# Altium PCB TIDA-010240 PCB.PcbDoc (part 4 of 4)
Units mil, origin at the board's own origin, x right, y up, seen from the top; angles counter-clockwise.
Board outline 5108.27 x 5374.02 mil, 4 copper layers (Top Layer, GND, PWR, Bottom Layer), stack 73.068 mil thick; 370 components, 162 nets, 1073 pads, 556 vias.
Unrouted connection lines stored in the file: 6.
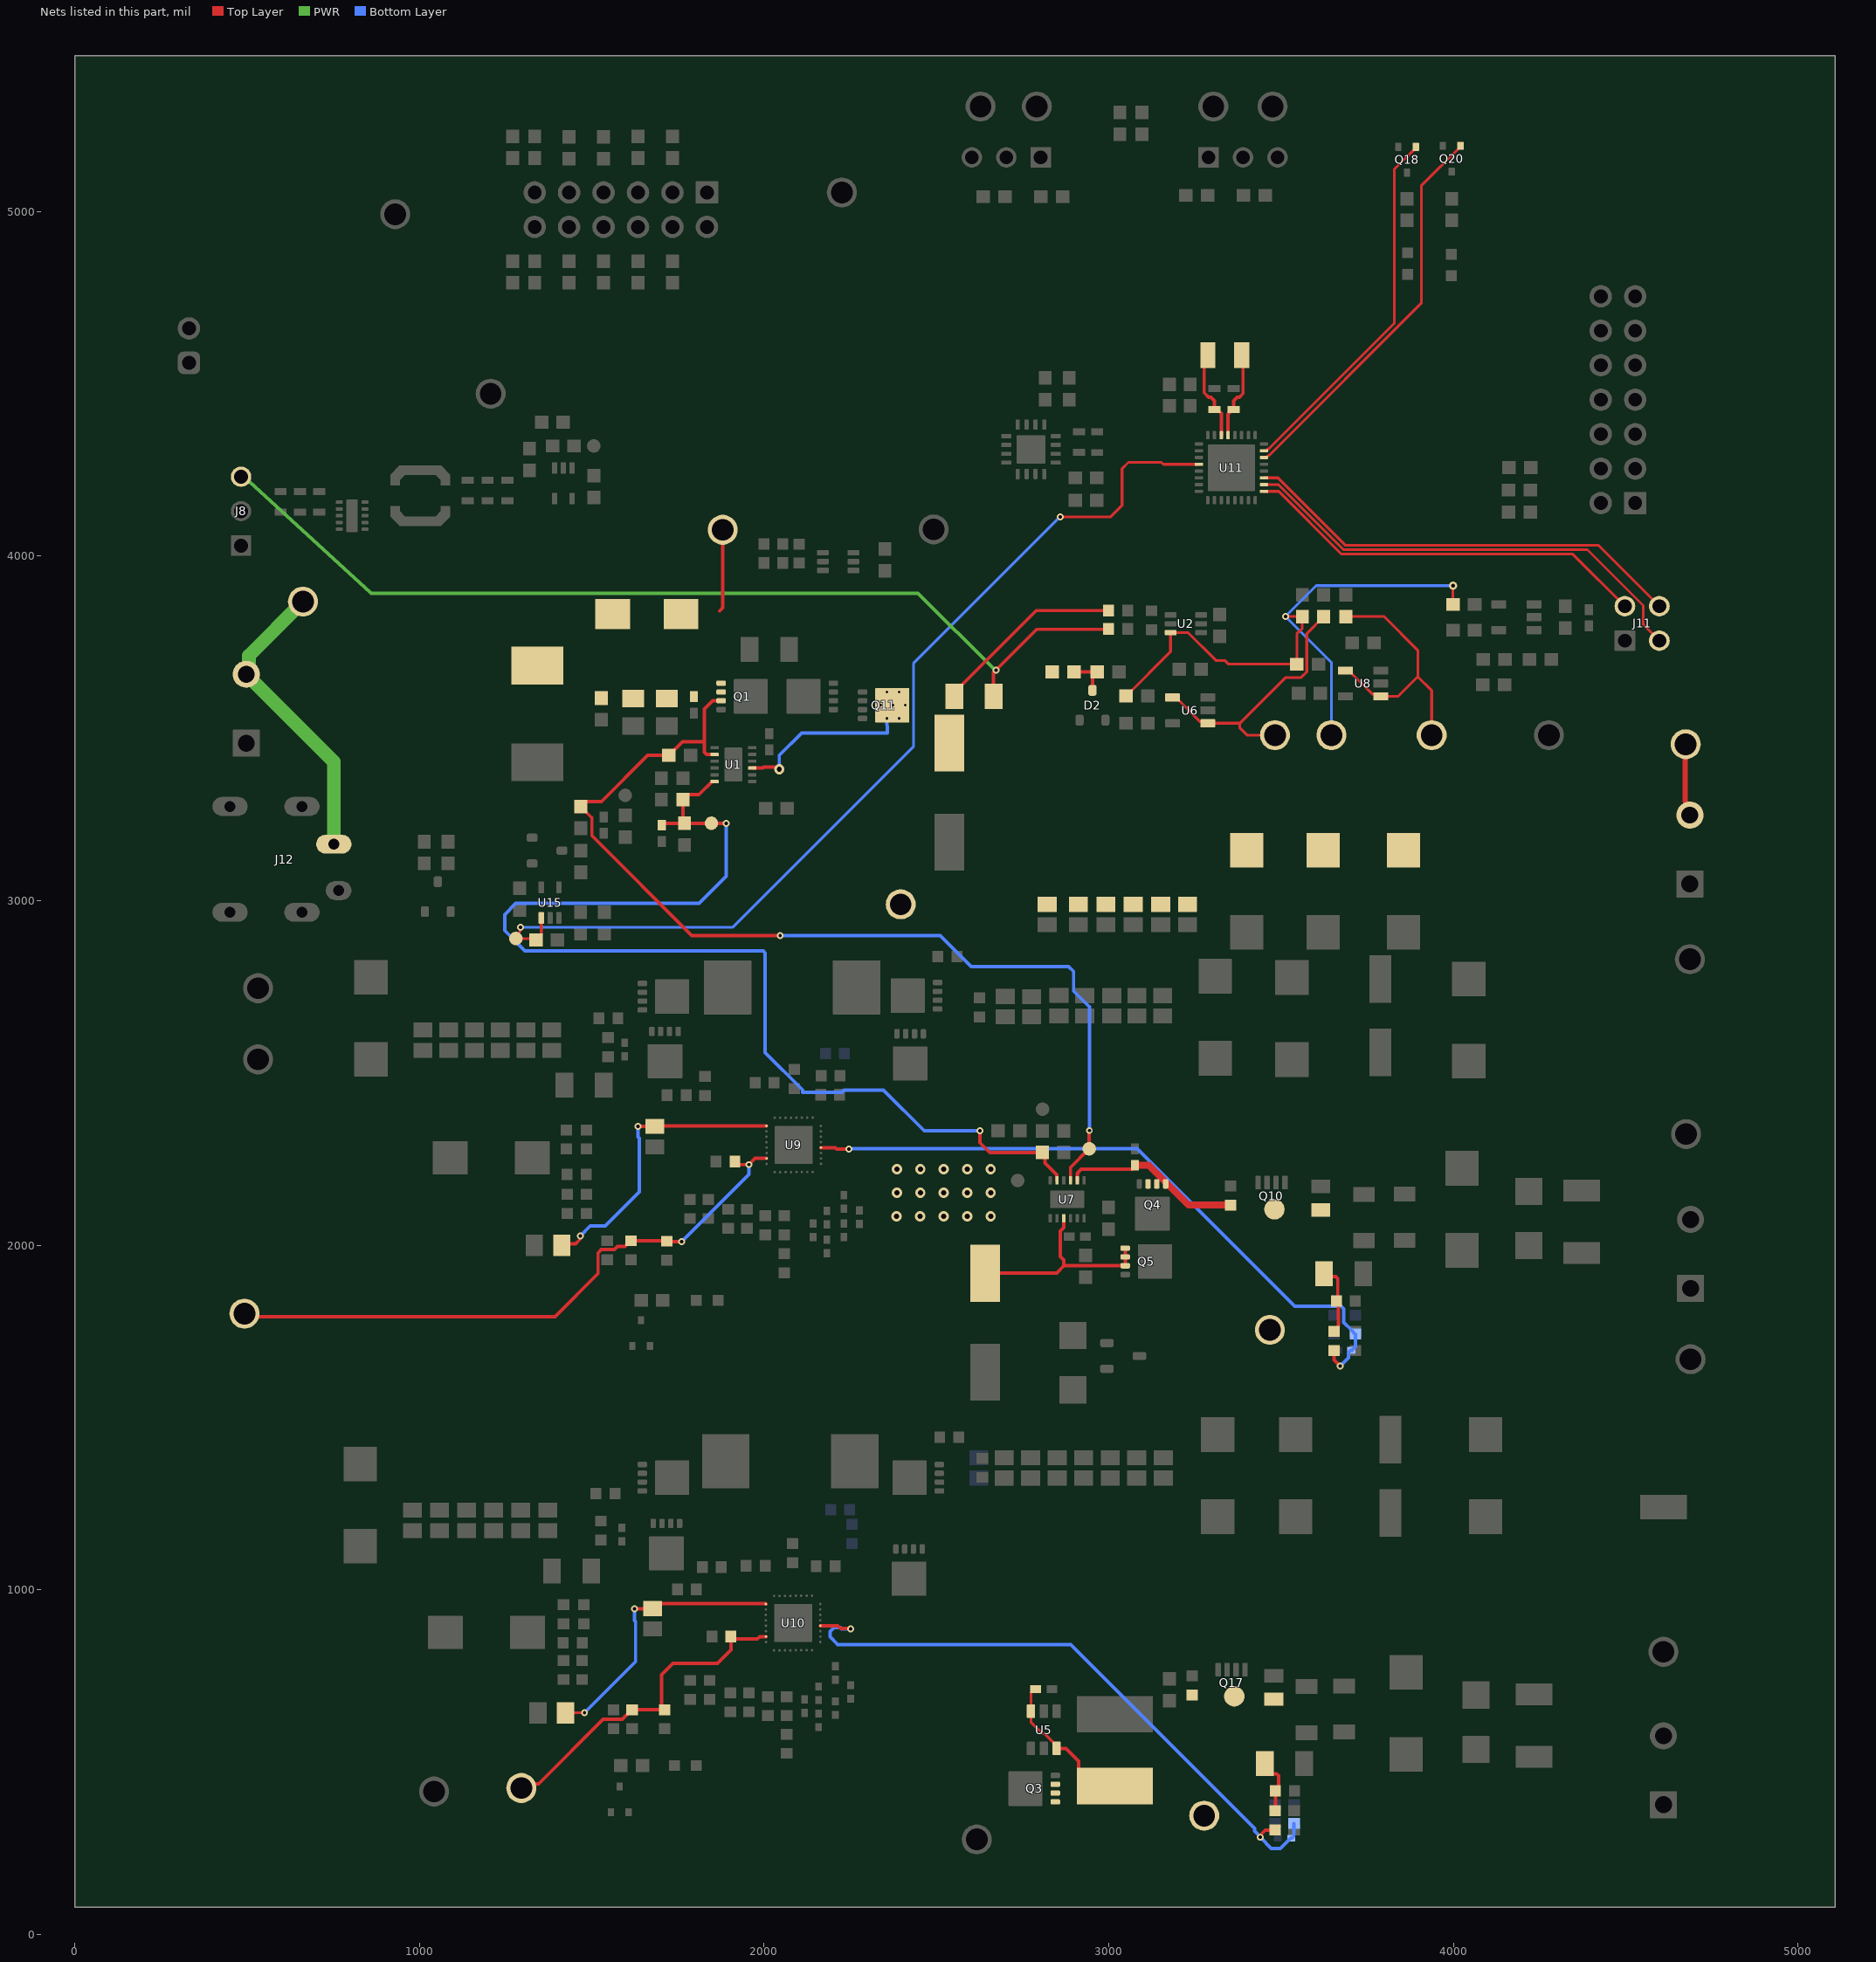
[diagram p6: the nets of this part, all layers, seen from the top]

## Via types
v1: diameter 30, hole 15, Top Layer to Bottom Layer, tented both sides, 281 vias
v2: diameter 19.68, hole 7.87, Top Layer to Bottom Layer, 102 vias
v3: diameter 20, hole 10, Top Layer to Bottom Layer, tented both sides, 99 vias
v4: diameter 24, hole 12, Top Layer to Bottom Layer, tented both sides, 19 vias
v5: diameter 23.62, hole 11.81, Top Layer to Bottom Layer, 18 vias
v6: diameter 19.68, hole 7.87, Top Layer to Bottom Layer, tented both sides, 14 vias
v7: diameter 28, hole 14, Top Layer to Bottom Layer, tented both sides, 13 vias
v8: diameter 25, hole 10, Top Layer to Bottom Layer, tented both sides, 8 vias
v9: diameter 18, hole 8, Top Layer to Bottom Layer, tented both sides, 2 vias

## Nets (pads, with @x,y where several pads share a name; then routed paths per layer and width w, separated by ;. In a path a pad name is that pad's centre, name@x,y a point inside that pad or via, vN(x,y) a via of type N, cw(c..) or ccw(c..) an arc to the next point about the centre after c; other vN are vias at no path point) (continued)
SRP_A: C65.1 C72.1 R28.1 U9.20 | length 1965.6
  Top Layer w10: U9.20@2165.04,2283.52 2206.64,2283.52 2210.95,2279.2 v3(2246.03,2279.2) ; R28.1@3653.86,1694.94 3653.87,1667.65 v3(3671.87,1649.65)
  Bottom Layer w10: v3(2246.03,2279.2) 2247.04,2280.22 3082.16,2280.22 3539.32,1823.06 3674.72,1823.06 3681.93,1815.85 3681.93,1776.11 3704.13,1753.91 3704.13,1752.93 3714.88,1742.18 C72.1@3715.87,1742.18 ; v3(3671.87,1649.65) 3696.05,1673.83 3696.05,1689.05 3701.93,1694.94 3705.87,1694.94 3710.71,1699.78 3710.71,1700.82 3715.84,1705.94 C72.1@3715.84,1742.15
SRP_B: C119.1 C126.1 R52.1 U10.20 | length 1887
  Top Layer w10: U10.20@2163.24,895.79 2213.54,895.79 2221.39,887.94 2250.63,887.94 v3(2251.55,887.03) ; v3(3439.56,281.74) 3441.09,283.27 3441.09,289.23 3454.23,302.36 3481.61,302.36 R52.1@3482.6,303.35
  Bottom Layer w10: v3(2251.55,887.03) 2224.94,887.03 2221.55,890.42 2202.93,890.42 2191.21,878.71 2191.21,863.55 2213.67,841.09 2889.61,841.09 3423.65,307.05 3423.65,299.77 3439.56,283.86 v3(3439.56,281.74) 3471.6,249.7 3498.22,249.7 3527.87,279.35 3531.81,279.35 3536.65,284.2 3536.65,290.24 3537.72,291.3 C126.1@3537.72,322.05
STATUS_LED0: Q20.1 U11.22 | length 1145.7
  Top Layer w8: U11.22@3450.52,4286.35 3457.41,4286.35 3463.17,4292.12 3464.91,4292.12 3907.04,4734.25 3907.04,5074.76 4020.59,5188.3 Q20.1@4020.59,5190.86
STATUS_LED1: Q18.1 U11.23 | length 1069.5
  Top Layer w8: U11.23@3450.52,4306.04 3457.41,4306.04 3463.17,4311.8 3464.91,4311.8 3828.74,4675.64 3828.74,5122.99 3891.17,5185.42 Q18.1@3891.17,5187.98
SYS_IAVG: R105.1 SYS_IAVG.1 U8.1 U8.4 | length 777.2
  Top Layer w8: U8.4@3686.65,3667.89 3696.49,3667.89 3764.49,3599.9 3782.2,3599.9 U8.1@3789.01,3593.09 3839.53,3593.09 3896.69,3650.25 ; R105.1@3687.98,3824.98 3798.97,3824.98 3896.69,3727.27 3896.69,3650.25 ; SYS_IAVG.1@3937.01,3480.63 3937.01,3609.93 3896.69,3650.25
SYS_IFLT: R104.1 SYS_IFLT.1 U6.1 U6.4 | length 787.8
  Top Layer w8: U6.4@3185.12,3589.9 3194.96,3589.9 3265.45,3519.41 3283.17,3519.41 U6.1@3287.48,3515.1 3380.41,3515.1 ; SYS_IFLT.1@3482.3,3480.63 3400.61,3480.63 3380.41,3500.82 3380.41,3515.1 ; R104.1@3623.39,3824.98 3623.39,3824 3574.59,3775.2 3574.59,3664.16 3558.48,3648.05 3513.36,3648.05 3380.41,3515.1
SYS_ISNS: R12.1 R14.1 R19.1 R106.1 SYS_ISNS.1 U2.6 | length 1831.4
  Top Layer w8: R14.1@3035.59,3608.25 3049.29,3594.55 R14.1@3050.28,3594.55 3051.26,3594.55 3179.41,3722.71 U2.6@3179.41,3778.22 3230.4,3778.22 3311.18,3697.43 3336.49,3697.43 3347.33,3686.59 R19.1@3542.95,3686.59 ; v3(3512.71,3825.14) 3561.5,3825.14 R106.1@3561.65,3824.98 3561.65,3790.45 3545.9,3774.7 R19.1@3545.9,3686.59 R19.1@3544.92,3686.59 ; R12.1@3998.85,3860.19 v4(3998.85,3914.3)
  Bottom Layer w8: SYS_ISNS.1@3645.99,3480.63 3645.99,3691.85 v3(3512.71,3825.14) 3601.87,3914.3 v4(3998.85,3914.3)
SYS_ISNS_N: C1.1 C2.1 C3.1 C4.1 C5.1 C6.1 C17.1 C155.1 C156.1 J8.3 J10.2 R2.1 R3.2 R15.2 VSYS.1 | length 3061.1
  Top Layer w10: R2.1@2671.28,3598.39 R2.1@2666.03,3593.14 2666.03,3662.65 2791.05,3787.66 2998.19,3787.66 R3.2@2999.58,3789.04
  Top Layer w15: VSYS.1@4672.97,3438.41 4672.97,3289.15 4674.07,3288.05 4674.07,3260.68 J10.2@4686.27,3248.49
  PWR w10: J8.3@492.28,4229 856.98,3895.15 859.82,3892.53 2446.64,3892.53 v3@2671.28,3667.89
  other v3: 2672.66,3669.28
SYS_ISNS_P: C7.1 C29.1 MUX_PWR.1 Q5.1 Q5.2 Q5.3 Q11.5 Q11.6 Q11.7 Q11.8 Q11.9 R2.2 R4.2 U1.9 U7.9 | length 1675.8
  Top Layer w10: U1.9@1965.61,3385.23 1996.69,3385.23 1999.47,3388.01 2032.32,3388.01 2038.48,3381.85 v1(2043.89,3381.85) ; R2.2@2551.86,3593.14 2551.86,3603.97 2790.08,3842.19 R4.2@2999.58,3842.19 ; C29.1@2641.15,1918.87 2848.7,1918.87 2869.99,1940.16 ; U7.9@2869.38,2078.74 2869.38,2050.85 2859.66,2041.13 2859.66,1967.3 2869.99,1956.97 2869.99,1940.16 ; Q5.1@3047.79,1991.67 Q5.2@3047.79,1966.08 Q5.3@3047.79,1940.49 2870.32,1940.49 2869.99,1940.16
  Bottom Layer w10: v1(2043.89,3381.85) 2043.89,3422.29 2108.83,3487.23 2357.68,3487.23 v2(2356.35,3529.06)
  other v1: 2384.48,2083.7 2452.72,2083.7 2520.96,2083.7 2589.2,2083.7 2657.43,2083.7 2385.33,2152.6 2453.36,2152.6 2521.38,2152.6 2589.41,2152.6 2657.43,2152.6 2385.33,2220.57 2453.36,2220.57 2521.38,2220.57 2589.41,2220.57 2657.43,2220.57
  other v2: 2391.98,3529.06 2338.54,3567.45 2374.17,3567.45 2356.35,3605.83 2391.98,3605.83
  other v6: 2409.8,3567.45
SYS_VSNS: D2.3 R15.1 R17.2 | length 126.7
  Top Layer w10: R15.1@2899.08,3664.16 R17.2@2966.46,3664.16 ; D2.3@2952.76,3610.76 2952.76,3650.46 R17.2@2966.46,3664.16 ; R17.2@2966.7,3664.16 R17.2@2966.46,3664.16
UCA1CLK: J11.2 U11.17 | length 1185.1
  Top Layer w8: U11.17@3450.52,4187.93 3493.39,4187.93 3675.41,4005.91 4346.54,4005.91 J11.2@4497.66,3854.79
UCA1SIMO: J11.4 U11.19 | length 1301.4
  Top Layer w8: U11.19@3450.52,4227.3 3490.79,4227.3 3686.18,4031.91 4420.54,4031.91 J11.4@4597.66,3854.79
UCA1SOMI: J11.3 U11.18 | length 1366.9
  Top Layer w8: U11.18@3450.52,4207.61 3492.09,4207.61 3680.79,4018.91 4388.59,4018.91 4550.76,3856.73 4550.76,3801.69 J11.3@4597.66,3754.79
UV/OV_SET: C154.1 R87.1 R88.2 R109.2 TP6.1 U1.6 U7.5 | length 3368.4
  Top Layer w10: C154.1@1703.34,3219.41 1708.59,3224.66 R88.2@1768.82,3224.66 ; U1.6@1856.16,3345.86 1849.04,3345.86 1810.81,3307.63 1777.96,3307.63 1764.26,3293.93 R87.1@1764.26,3292.95 1764.26,3229.23 R88.2@1768.82,3224.66 ; v3(1889.51,3224.66) TP6.1@1846.99,3224.66 R88.2@1768.82,3224.66 ; v3(2626.4,2332.27) 2626.4,2297.57 2654.7,2269.28 R109.2@2807.64,2269.28 ; R109.2@2814.96,2253.94 2814.96,2238.88 2849.7,2204.15 U7.5@2849.7,2188.18
  Bottom Layer w10: v3(1889.51,3224.66) 1889.51,3070.61 1811.02,2992.13 1279.53,2992.13 1247.12,2959.71 1247.12,2913.39 1306.17,2854.33 1997.43,2854.33 2003.29,2848.47 2003.29,2558.97 2111.35,2450.9 2111.35,2443.88 2225.86,2443.88 2232.18,2450.2 2346.69,2450.2 2464.62,2332.27 v3(2626.4,2332.27)
VBAT_A: C27.1 C44.1 C59.1 Q4.1 Q4.2 Q4.3 Q10.5-6-7-8 R23.1 R25.2 R28.2 U7.2 VBAT_A.1 | length 775.6
  Top Layer w10: U7.2@2908.75,2188.18 2908.75,2207.4 2909.97,2208.61 2909.97,2210.34 2920.21,2220.59 3068.21,2220.59 3076.02,2228.4 C27.1@3076.02,2232.34 ; R23.1@3645.41,1885.96 3644.92,1885.96 3624.33,1906.55 R23.1@3624.33,1917.38 3632.94,1908.77 3658.67,1908.77 3664.53,1902.91 3664.53,1842.72 C44.1@3660.26,1838.45 3666.89,1831.82 3666.89,1766.66 3665.59,1765.36 3665.59,1760.8 3654.84,1750.05 R28.2@3653.86,1750.05
  Top Layer w20: C27.1@3076.02,2232.34 3116.16,2232.34 3231.9,2116.6 C59.1@3353.6,2116.6
VBAT_B: C22.1 C24.1 C98.1 C113.1 Q3.1 Q3.2 Q3.3 Q17.5-6-7-8 R47.1 R49.2 R52.2 U5.3 U5.6 VBAT_B.1 | length 609
  Top Layer w8: C24.1@2787.94,711.8 2784,711.8 2774.16,701.96 U5.3@2774.16,647.82 2774.16,616.14 2807.25,583.04 2813.35,583.04 2848.96,547.43 U5.6@2848.96,539.55
  Top Layer w10: U5.6@2848.96,539.55 2875.77,539.55 2913.02,502.31 2913.02,478.45 2961.17,430.3 C22.1@3018.25,430.3 ; R47.1@3453.07,495.89 3453.07,486.96 3473.66,466.37 3486.77,466.37 3492.63,460.51 3492.63,425.05 C98.1@3483.77,416.19 3483.77,359.64 R52.2@3482.6,358.47
VBUS_A: C74.1 R32.1 U9.1 | length 861.2
  Top Layer w8: R32.1@1413.04,1999.95 R32.1@1415.42,1997.56
  Top Layer w10: R32.1@1415.42,1998.18 1421.69,2004.45 1453.04,2004.45 1464.86,2016.27 1464.86,2025.88 v3(1466.39,2027.41) ; v3(1634.12,2345) C74.1@1683,2345 ; C74.1@1683.07,2344.93 1684.65,2346.51 U9.1@2006.74,2346.51
  Bottom Layer w10: v3(1466.39,2027.41) 1495.37,2056.39 1539.08,2056.39 1638.07,2155.38 1638.07,2310.65 1634.12,2314.61 v3(1634.12,2345)
VBUS_B: C128.1 R56.1 U10.1 | length 807.1
  Top Layer w8: R56.1@1423.65,642.84 1424.44,643.63 v3(1478.87,643.63)
  Top Layer w10: v3(1624.27,945.26) 1676.13,945.26 1690.98,960.11 2003.61,960.11 U10.1@2004.94,958.78
  Bottom Layer w10: v3(1478.87,643.63) 1627.07,791.83 1627.07,907.64 1624.27,910.44 v3(1624.27,945.26)
VDDA_A: C79.1 R35.2 R37.2 U9.7 VDDA_A.1 | length 1793.1
  Top Layer w10: VDDA_A.1@502.59,1792.4 1392.85,1792.4 1518.06,1917.62 1518.06,1977.78 1527.54,1987.26 1565.67,1987.26 1575.04,1996.63 1596.09,1996.63 1612.46,2013 1716.61,2013 R35.2@1717.74,2011.87 1718.94,2010.66 v3(1761.11,2010.66) ; C79.1@1915.26,2242.87 1923.9,2234.23 v3(1955.61,2234.23) 1973.4,2252.02 U9.7@2007.15,2252.02
  Bottom Layer w10: v3(1761.11,2010.66) 1955.61,2205.16 v3(1955.61,2234.23)
VDDA_B: C133.1 R59.2 R61.2 U10.7 VDDA_B.1 | length 997.6
  Top Layer w8: VDDA_B.1@1305.59,411.96 VDDA_B.1@1305.59,414.64
  Top Layer w10: VDDA_B.1@1295.49,424.74 1307.96,437.21 1345.76,437.21 1533.08,624.53 1588.49,624.53 1616.05,652.09 R61.2@1617.04,652.09 1712.6,652.09 1702.12,662.57 1702.12,753.73 1734.98,786.6 1864.17,786.6 1903.45,825.87 C133.1@1903.45,864.68 1910.56,857.57 1980.55,857.57 1987.27,864.29 U10.7@2005.35,864.29
Vin: C9.1 C10.1 D1.2 J1.2 J12.3 L1.1 Vin.1 | length 877.2
  PWR w40: Vin.1@661.86,3868.11 504.88,3711.13 504.88,3664.63 J1.2@497.47,3657.22 751.49,3403.2 J12.3@751.49,3164.17
VIN_FLT: C11.1 C12.1 L1.2 Q1.1 Q1.2 Q1.3 R96.2 R103.1 TP7.1 U1.2 U7.3 VIN_FLT.1 | length 3220.5
  Top Layer w10: L1.2@1759.27,3832.21 L1.2@1771.81,3844.74 ; U1.2@1856.16,3424.6 1832.61,3424.6 1826.75,3430.46 1826.75,3461.64 ; 1870.91,3840.89 1879.92,3849.9 VIN_FLT.1@1879.92,4076.52 ; Q1.3@1875.15,3580.35 1851.12,3580.35 1826.75,3555.98 1826.75,3461.64 ; v3(2046.5,2898.72) 1790.07,2898.72 1500.32,3188.47 1500.32,3240.36 1468.18,3272.49 R96.2@1468.18,3273.48 1468.18,3274.46 1481.88,3288.16 1528.21,3288.16 1662.33,3422.29 R103.1@1723.35,3422.29 1724.33,3422.29 1763.69,3461.64 1826.75,3461.64 ; U7.3@2889.07,2188.18 2889.07,2226.15 2942.91,2279.99 TP7.1@2942.91,2283.46 ; TP7.1@2943.14,2280.22 2943.41,2280.48 2943.41,2332.73 v3(2943.67,2332.99)
  Bottom Layer w10: v3(2046.5,2898.72) 2510.77,2898.72 2600.45,2809.04 2883.86,2809.04 2897.97,2794.92 2897.97,2737.72 2943.67,2692.02 v3(2943.67,2332.99)
VIN_LOW: R101.2 TP11.1 U11.4 U15.1 | length 2903
  Top Layer w8: v3(1293.41,2923.23) 1291.5,2921.31 1291.5,2910.07 1279.53,2898.09 TP11.1@1279.53,2890.14 1333.77,2890.14 R101.2@1337.71,2886.21 1338.69,2886.21 1353.45,2900.97 U15.1@1353.45,2950.18 ; v3(2859.01,4114.17) 3005.65,4114.17 3038.81,4147.34 3038.81,4254.17 3056.99,4272.35 3153.06,4272.35 3158.74,4266.67 U11.4@3261.54,4266.67
  Bottom Layer w8: v3(1293.41,2923.23) 1909.43,2923.23 2433.25,3447.04 2433.25,3688.41 v3(2859.01,4114.17)
Xin: C146.1 U11.30 Y1.1 | length 265.1
  Top Layer w10: Y1.1@3287.28,4583.23 3276.85,4572.81 3276.85,4474.39 3289.75,4461.49 3296.39,4461.49 3306.82,4451.06 C146.1@3306.82,4426.06 3314.32,4426.06 3326.5,4413.88 U11.30@3326.5,4351.31
Xout: C147.1 U11.29 Y1.2 | length 259.8
  Top Layer w10: U11.29@3346.19,4351.31 3346.19,4412.35 3349.63,4415.79 3349.63,4421.06 3354.63,4426.06 C147.1@3362.13,4426.06 3362.13,4451.06 3372.56,4461.49 3379.2,4461.49 3389.63,4471.92 3389.63,4579.31 Y1.2@3385.7,4583.23
pads on no net: J4.3 J4.5 J4.6 J4.8 J4.10 J4.11 J4.12 J4.13 J4.14 Q1.9A Q1.9B Q1.9C Q1.9D Q2.9A Q2.9B Q2.9C Q2.9D Q3.9A Q3.9B Q3.9C Q3.9D Q4.9A Q4.9B Q4.9C Q4.9D Q5.9A Q5.9B Q5.9C Q5.9D Q6.9A Q6.9B Q6.9C Q6.9D Q7.9A Q7.9B Q7.9C Q7.9D Q8.9A Q8.9B Q8.9C Q8.9D Q9.9A Q9.9B Q9.9C Q9.9D Q11.9A Q11.9B Q11.9C Q11.9D Q13.9A Q13.9B Q13.9C Q13.9D Q14.9A Q14.9B Q14.9C Q14.9D Q15.9A Q15.9B Q15.9C Q15.9D Q16.9A Q16.9B Q16.9C Q16.9D U1.13 U7.13 U9.15 U10.15 U11. U12.17@2752.08,4287.73 U12.17@2752.08,4332.57 U12.17@2796.92,4287.73 U12.17@2796.92,4332.57 U13.7 U13.11@804.52,4092.17 U13.11@804.52,4142.56
copper on no net:
  other v2: 2839.85,2133.46 2879.22,2133.46 2918.59,2133.46 1910.89,3355.7 1910.89,3395.07 1910.89,3434.44
  other v7: 2450.44,2813.81

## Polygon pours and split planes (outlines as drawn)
SYS_ISNS_P on Top Layer "TOP_LAYER_SYS_ISNS_P_P001" (solid, pour order 1): 2322.83,3641.73 2588.58,3641.73 2588.58,3345.86 2322.83,3345.86
NetQ2_1 on Top Layer "TOP_LAYER_NETQ2_1_P000" (solid, pour order 0): 2184.81,3624.63 2304.28,3624.63 2304.28,3520.33 2305.2,3519.41 2300.03,3514.24 2184.81,3514.24
SYS_ISNS_N on Top Layer "TOP_LAYER_SYS_ISNS_N_P002" (solid, pour order 2): 2639.47,3630.46 2691.39,3682.38 2860.05,3682.38 2865.29,3677.13 2865.29,3309.09 2639.77,3309.09 2639.63,3309.22
GND on Top Layer "GND" (solid, pour order 85): -9.84,5452.76 5118.11,5452.76 5118.11,78.74 -9.84,78.74
SYS_ISNS_N on Top Layer "TOP_LAYER_SYS_ISNS_N_P081" (solid, remove dead copper, pour order 81): 2732.05,3399.99 2721.22,3389.17 2721.22,3246.96 2721.22,2972.48 4746.85,2972.48 4746.85,3349.87 4595.3,3349.87 4595.3,3420.35 2747.8,3420.35 2747.8,3414.37 2721.22,3387.8
BattORR on Top Layer "TOP_LAYER_BATTORR_P012" (solid, remove dead copper, pour order 12): 3073.81,2144.16 3073.81,1757.75 3306.26,1757.75 3306.26,1932.63 3186.26,1932.63 3186.26,2144.16
SYS_ISNS_P on Top Layer "TOP_LAYER_SYS_ISNS_P_P013" (solid, remove dead copper, pour order 13): 3065.98,1997.79 3065.98,1932.08 2949.8,1932.08 2824.18,1859.31 2307.71,1855.94 2307.73,1960.71 2307.79,2257.42 2691.38,2257.42 2691.38,2019.27 2824.18,2019.27 2840.81,1992.46 2855.7,1992.46 2989.16,1997.79
VIN_FLT on Top Layer "TOP_LAYER_VIN_FLT_P064" (solid, remove dead copper, pour order 64): 1655.57,3436.74 1655.57,3398.71 1664.13,3398.71 1672.7,3398.71 1870.91,3398.71 1869.61,3427.72 1836.89,3427.72 1833.96,3456.09 1674.92,3456.09
NetC87_1 on Top Layer "TOP_LAYER_NETC87_1_P025" (solid, remove dead copper, pour order 25): 2538.84,1353.91 2536.91,1147.59 2354.34,1147.59 2349.84,1147.59 2349.84,1054.85 2349.84,741.2 4230.01,741.2 4230.01,1092.43 4230.01,1353.91
IN_ISNS_N on Top Layer "TOP_LAYER_IN_ISNS_N_P033" (solid, remove dead copper, pour order 33): 2294.1,3473.45 2176.22,3473.45 2176.22,3775.81 2044.03,3775.81 2044.03,3765.32 2044.03,3743.67 2044.03,2949.53 2294.1,2949.53
VBAT_B on Top Layer "TOP_LAYER_VBAT_B_P027" (solid, remove dead copper, pour order 27): 3147.37,702.39 3166.8,702.39 3508.2,702.39 3509.15,531.48 3479.19,530.83 3478.54,455.28 3423.83,455.28 3423.83,267.54 2833.96,267.54 2833.96,436.18 2866.48,436.18 2909.63,471.95 3147.37,471.95
NetC33_1 on Top Layer "TOP_LAYER_NETC33_1_P010" (solid, remove dead copper, pour order 10): 2540.61,2692.36 2540.61,2575.15 2375.49,2575.15 2375.49,2403.03 2375.49,2292.88 3445.59,2292.88 3449.34,2151.82 3662.31,2145.1 3658.74,2291.88 4105.57,2289.77 4105.57,2367.15 4105.57,2460.87 4105.57,2474.04 4105.57,2692.36
VBAT_A on Top Layer "TOP_LAYER_VBAT_A_P016" (solid, remove dead copper, pour order 16): 3320.14,2137.34 3323.13,2134.36 3649.09,2134.36 3649.09,1871.12 3625.71,1871.12 3625.71,1675.25 3674.53,1675.25 3320.14,1675.25 3320.14,2104.34 3211.92,2104.34 3323.13,2101.36 3309.36,2093.57 3329.42,2104.34 3329.42,2128.07
NetC56_2 on Top Layer "TOP_LAYER_NETC56_2_P006" (solid, remove dead copper, pour order 6): 2201.69,2840.56 2188.95,2827.82 2188.95,2654.57 2188.95,2401.03 2248.36,2402.62 2251.02,2654.57 2359.37,2654.57 2397.64,2632.57 2397.64,2591.18 2478.07,2591.18 2474.31,2594.94 2474.31,2610.69 2474.31,2819.73 2453.48,2840.56
Vin on Top Layer "TOP_LAYER_VIN_P036" (solid, remove dead copper, pour order 36): 1649.04,3884.11 1510.23,4022.92 311.14,4038.27 311.14,3884.11 311.14,3558.69 446.72,3546.78 1649.04,3546.78 1660.49,3558.69 1660.49,3875.87 1649.04,3887.33
NetC107_1 on Top Layer "TOP_LAYER_NETC107_1_P020" (solid, remove dead copper, pour order 20): 1763.77,1156.01 1691.07,1156.01 1650.75,1153.54 1648.28,1156.01 1474.04,1156.01 1474.04,1111.06 1472.71,1019.14 1512.12,1019.29 1512.12,979.73 1586.93,979.17 1665.94,979.17 1665.94,1026.1 1709.08,1026.1 1770.41,1026.1 1770.41,1083.65 1772.89,1086.13 1763.77,1095.26
NetC109_1 on Top Layer "TOP_LAYER_NETC109_1_P023" (solid, remove dead copper, pour order 23): 1980.62,1386.59 1982.85,1449.94 1683.88,1449.94 1683.88,1335.27 1686.24,1332.9 1686.24,1176.87 1754.32,1176.87 1961.92,1176.87 1980.62,1213.12 1982.24,1384.62
NetC110_2 on Top Layer "TOP_LAYER_NETC110_2_P024" (solid, remove dead copper, pour order 24): 2206.74,1452.15 2184.57,1429.99 2184.57,1256.74 2355,1256.74 2393.32,1212.86 2393.32,1097.89 2469.94,1097.89 2469.94,1201.59 2469.94,1212.86 2469.94,1421.9 2439.68,1452.15
VBAT_A on Top Layer "TOP_LAYER_VBAT_A_P015" (solid, remove dead copper, pour order 15): 3036.02,2161.77 3036.84,2162.59 3176.62,2162.59 3176.62,2249.79 3106.94,2251.24 3105.49,2249.79 3036.02,2249.79 3036.02,2173.82 3033.92,2171.71
IN_ISNS_N on Top Layer "TOP_LAYER_IN_ISNS_N_P008" (solid, remove dead copper, pour order 8): 748.85,2595.11 813.01,2595.11 817.61,2595.11 829.35,2595.11 1445.41,2591.18 1445.41,2571.9 1449.08,2575.57 1449.08,2429.45 1394.25,2429.21 1394.25,2317.79 1265.79,2317.79 1265.79,2191.85 1364.22,2191.85 1369.92,1947.89 748.85,1947.89
NetC44_2 on Top Layer "TOP_LAYER_NETC44_2_P017" (solid, remove dead copper, pour order 17): 3712.53,2049.34 3712.12,1875.48 3740.25,1875.48 3740.25,1582.78 4433,1582.78 4433,2049.34
NetC98_2 on Top Layer "TOP_LAYER_NETC98_2_P026" (solid, remove dead copper, pour order 26): 3542.11,629.01 3541.71,448.11 3600.98,449.42 3600.98,270.5 4298.88,270.5 4298.88,583.19 3757.58,583.19 3711.75,629.01 3523.94,629.01
NetC148_1 on Top Layer "TOP_LAYER_NETC148_1_P031" (solid, remove dead copper, pour order 31): 462.28,4147.13 462.28,4107.67 776.94,4106.13 778.44,4107.63 778.44,4144.15 775.46,4147.13
NetL4_1 on Top Layer "TOP_LAYER_NETL4_1_P084" (solid, remove dead copper, pour order 84): 1104.35,4145.47 1104.35,4074.95 946.3,4074.95 890.65,4130.59 890.65,4148.38 1091.9,4148.38
IN_ISNS_N on Top Layer "TOP_LAYER_IN_ISNS_N_P029" (solid, remove dead copper, pour order 29): 748.85,1173.26 748.85,1187.5 778.09,1187.5 794.43,1187.5 1402.8,1187.5 1410.22,1180.07 1410.22,1164.02 1410.22,1017.27 1360.23,1017.27 1360.48,935.39 1230.51,931.86 1230.51,786.17 1355.66,786.17 1355.66,587.52 748.85,587.52
3.3V_Buck on Top Layer "TOP_LAYER_3.3V_BUCK_P083" (solid, remove dead copper, pour order 83): 746.56,4551.16 300.81,4551.16 300.81,4461.16 826.77,4461.16 826.77,4171.41 826.77,4148.38 854.79,4148.38 854.79,4171.41 1021.63,4169.85 1036.35,4184.57 1039.6,4181.32 1281.48,4181.32 1281.48,4551.16
VIN_FLT on Top Layer "TOP_LAYER_VIN_FLT_P042" (solid, remove dead copper, pour order 42): 1712,3885.72 1701.54,3875.26 1701.54,3857.05 1686.68,3842.19 1689.28,3839.59 1689.28,3546.78 1753.79,3546.78 1774.73,3567.72 1774.73,3568.43 1891.31,3568.43 1895.25,3572.37 1895.25,3868.28 1879.41,3884.11 1715.15,3884.11
BattORR on Top Layer "TOP_LAYER_BATTORR_P030" (solid, remove dead copper, pour order 30): 2814.94,360.69 2805.69,369.94 2805.69,470.3 2788.64,470.3 2786.56,472.38 2787.38,473.2 2787.38,562.21 2738.2,562.21 2725.69,574.73 2727.51,576.54 2727.51,762.57 2413.13,762.57 2393.32,742.76 2393.32,366.37 2803.28,366.37 2815.33,378.41 2805.99,387.74 2805.99,469.38
no net on Top Layer "TOP_LAYER_NONET_P011" (solid, remove dead copper, pour order 11): 3018.3,2147.68 2997.79,2127.16 2997.5,2127.16
NetC55_1 on Top Layer "TOP_LAYER_NETC55_1_P009" (solid, remove dead copper, pour order 9): 1982.54,2819.14 1963.84,2837.84 1685.8,2837.84 1685.8,2767.81 1688.16,2765.45 1688.16,2609.42 1756.24,2609.42 1963.84,2609.42 1982.54,2645.66 1984.16,2817.17
NetC53_1 on Top Layer "TOP_LAYER_NETC53_1_P007" (solid, remove dead copper, pour order 7): 1758.73,2581.73 1750.96,2589.5 1673.92,2589.5 1647.53,2563.12 1645.06,2565.59 1507.37,2565.59 1508.37,2525.69 1507.91,2428.43 1507.37,2316.26 1583.72,2316.52 1583.72,2402.36 1661.45,2480.09 1662.72,2478.82 1767.2,2478.82 1767.2,2493.22 1769.68,2495.7 1760.55,2504.83 1760.55,2580.51
GND on Bottom Layer "BOTTOM_LAYER_GND_P086" (solid, pour order 86): -9.84,5452.76 5118.11,5452.76 5118.11,78.74 -9.84,78.74
IN_ISNS_N on Bottom Layer "BOTTOM_LAYER_IN_ISNS_N_P080" (solid, remove dead copper, pour order 80): 2051.37,3780.54 2054.8,3777.11 2176.22,3777.11 2176.22,3474.21 2047.28,3474.21 2047.28,3777.59
NetC109_1 on Bottom Layer "BOTTOM_LAYER_NETC109_1_P076" (solid, remove dead copper, pour order 76): 1691.07,1433.89 1968.25,1433.89 1980.62,1421.52 1980.62,1195.57 1961.92,1176.87 1955.9,1182.89 1696.23,1182.89 1696.23,1183.78 1683.84,1196.17 1683.88,1196.21 1683.88,1424.9 1692.07,1433.09
NetC55_1 on Bottom Layer "BOTTOM_LAYER_NETC55_1_P073" (solid, remove dead copper, pour order 73): 1685.8,2837.84 1963.84,2837.84 1963.84,2837.48 1984.16,2817.17 1982.54,2815.55 1982.54,2628.12 1963.84,2609.42 1691.94,2609.42 1691.94,2831.69
NetC110_2 on Bottom Layer "BOTTOM_LAYER_NETC110_2_P075" (solid, remove dead copper, pour order 75): 2197.32,1442.73 2449.1,1442.73 2469.94,1421.9 2469.94,1279.47 2462.99,1272.52 2184.94,1272.52 2184.94,1429.62 2184.57,1429.99
NetC56_2 on Bottom Layer "BOTTOM_LAYER_NETC56_2_P072" (solid, remove dead copper, pour order 72): 2201.69,2840.56 2453.48,2840.56 2474.31,2819.73 2474.31,2660.77 2441.64,2660.77 2418.03,2660.77 2392.33,2660.77 2378.17,2657.23 2375.51,2654.57 2188.95,2654.57 2188.95,2827.82
NetC107_1 on Bottom Layer "BOTTOM_LAYER_NETC107_1_P077" (solid, remove dead copper, pour order 77): 1764.55,1152.54 1762.81,1154.29 1615.4,1154.29 1615.4,1021.46 1624.7,1012.16 1762.55,1012.16 1762.55,1151.05 1764.4,1152.91
NetC33_1 on Bottom Layer "BOTTOM_LAYER_NETC33_1_P052" (solid, remove dead copper, pour order 52): 2378.46,2582.25 2378.46,2445.79 2453.83,2370.42 2880.59,2370.42 2880.59,2687.76 2597.29,2687.76 2597.29,2585.18 2479.88,2582.25
NetC53_1 on Bottom Layer "BOTTOM_LAYER_NETC53_1_P074" (solid, remove dead copper, pour order 74): 1760.4,2580.87 1759.55,2581.73 1661.21,2581.73 1645.06,2565.59 1507.37,2565.59 1507.37,2363.12 1583.72,2363.38 1583.72,2364 1765.66,2364
NetC87_1 on Bottom Layer "BOTTOM_LAYER_NETC87_1_P059" (solid, remove dead copper, pour order 59): 2366.98,1088.75 2366.98,972.7 2383.46,956.22 2802.36,956.22 2802.36,1352.54 2591.22,1352.54 2587.09,1090.92
SYS_ISNS_P on Bottom Layer "BOTTOM_LAYER_SYS_ISNS_P_P078" (solid, remove dead copper, pour order 78): 1914.98,3789.04 1918.42,3785.61 2023.2,3785.61 2023.2,3472.95 2026.64,3469.51 2021.09,3463.97 1910.89,3463.97 1910.89,3786.09
IN_ISNS_N on Bottom Layer "BOTTOM_LAYER_IN_ISNS_N_P038" (solid, remove dead copper, pour order 38): 767.02,2565.96 789.43,2588.36 1397.8,2588.36 1443.52,2542.64 1443.52,2324.56 1153.33,2324.56 1153.33,2178.87 1358.83,2178.87 1358.83,1950.99 767.02,1950.99
IN_ISNS_N on Bottom Layer "BOTTOM_LAYER_IN_ISNS_N_P014" (solid, remove dead copper, pour order 14): 759.4,1173.26 763.85,1173.26 786.26,1195.66 794.43,1187.5 1402.8,1187.5 1418.25,1172.04 1410.22,1164.02 1418.25,931.86 1230.51,931.86 1230.51,786.17 1355.66,786.17 1355.66,574.73 759.4,574.73 759.4,853.4
3.3V on PWR "PWR_3.3V_P044" (solid, remove dead copper, pour order 44): 308.33,4707.11 308.33,4629.96 308.33,4569.31 308.33,321.65 421.75,323.12 2302.13,321.65 2302.13,565.21 421.75,565.21 421.75,3980.89 2811.03,3986.66 3728.16,3986.66 3728.16,4571.34 3728.16,3458.8 4286.98,3458.8 4296.03,4843.42 4030.74,4843.42 3734.35,4846.83 3728.16,4707.11 421.75,4707.11
SYS_ISNS_P on PWR "PWR_SYS_ISNS_P_P055" (solid, remove dead copper, pour order 55): 2305,1724.35 2305,3875.84 3488.6,3875.84 3488.6,2210.42 2942.16,2213.15 2943.53,1683.13 2315.16,1683.13 2304.43,1693.86
no net on PWR "PWR_NONET_P057" (solid, remove dead copper, pour order 57): 3649.1,3414.39 3544.55,3414.39 3544.55,3246.96 3649.1,3246.96 4123.37,3246.96 4123.37,3414.39 4047.54,3414.39
BattORR on PWR "PWR_BATTORR_P054" (solid, remove dead copper, pour order 54): 2413.13,762.57 2393.32,742.76 2393.32,385.12 2419.98,358.47 4389.76,358.47 4389.76,2145.92 2967.4,2145.92 2967.4,1968.62 2967.4,758.56
IN_ISNS_N on PWR "PWR_IN_ISNS_N_P056" (solid, remove dead copper, pour order 56): 2281.74,3197.82 2281.74,3208.05 2277.8,3473.05 773.65,3469.12 521.8,3468.46 510.31,597.56 2277.8,597.56 2277.8,2952.96
GND on GND "GND" (solid, pour order 82): -9.84,5452.76 5118.11,5452.76 5118.11,78.74 -9.84,78.74

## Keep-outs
Keep-Out Layer:
  text ".Layer_Name" at 577,-858.49 h60

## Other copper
Top Layer:
  text ".Layer_Name" at 577,-858.49 h60
Bottom Layer:
  text ".Layer_Name" at 577,-858.49 h60

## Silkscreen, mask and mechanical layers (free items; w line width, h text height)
Top Overlay:
  text "This document can handle board shapes up to 7.9in x 10in, although" at 5917.72,7078.54 h60
  text "our panel vendors top out at 7in x 10in." at 5917.72,6954.48 h60
  text "To re-size the board shape, do the following:" at 5972.72,6830.43 h60
  text "Select lines on M1 Board Outline and delete (easy in single layer mode...shift+s)" at 6032.72,6706.37 h60
  text "Draw a rectangle using lines (example will be for a 4\" x 6\" board" at 6032.72,6582.31 h60
  text "Enter Place Line mode (keyboard pl)" at 6242.72,6458.25 h60
  text "keyboard jo to jump to origin, hit enter" at 6242.72,6334.19 h60
  text "keyboard jl to jump to location, set x to 6000, hit enter twice" at 6242.72,6210.13 h60
  text "keyboard jl to jump to location, set x to 6000 and y to 4000, hit enter twice" at 6242.72,6086.07 h60
  text "keyboard jl to jump to location, set x to 0 and y to 4000, hit enter twice" at 6242.72,5962.01 h60
  text "keyboard jo to jump to origin, hit enter" at 6242.72,5837.95 h60
  text "Hit ESC twice to exit place line mode" at 6242.72,5713.9 h60
  text "Select lines on M1 Board Outline" at 6032.72,5569.84 h60
  text "Menu Design|Board Shape|Define from Selected Objects (keyboard dsd)" at 6032.72,5465.78 h60
  text "'.PRJ_Number'.PCB_Rev" at 236.22,5167.27 h108.27
  text "If you re-size the board, don't forget to move the drill table strings on the" at 5917.72,5146.54 h60
  text "Drill Drawing Layer...they should be just to the right of your board shape" at 6110.72,5040.54 h60
  text "3.3V3" at 114.52,4576.62 h72.83
  text "Vin / +19 V" at 112.8,3619.4 h72.83
  text "GND" at 157.43,3362.51 h72.83
  text "VSYS Out" at 4764.31,3362.88 h72.83
  text "GND" at 4874.67,2979.14 h72.83
  text "VBat_A Out" at 4745.2,2209.75 h72.83
  text "GND" at 4891.68,1843.29 h72.83
  text "VBat_B Out" at 4680.69,710.47 h72.83
  text "GND" at 4832.62,341.02 h72.83
  text ".Layer_Name" at 577,-858.49 h60
Bottom Overlay:
  text ".Layer_Name" at 577,-858.49 h60
Top Paste:
  text ".Layer_Name" at 577,-858.49 h60
Bottom Paste:
  text ".Layer_Name" at 577,-858.49 h60
Top Solder:
  text ".Layer_Name" at 577,-858.49 h60
  text ".Layer_Name" at 577,-858.49 h60
Bottom Solder:
  text ".Layer_Name" at 577,-858.49 h60
Drill Guide:
  text ".Layer_Name" at 577,-858.49 h60
M1 Board Outline:
  lines w10: -9.84,78.74 5118.11,78.74 5118.11,5452.76 -9.84,5452.76 -9.84,78.74
  text ".Layer_Name" at 577,-858.49 h60
M2 Board Dimensions:
  rectangle: 0,-275 125,-150
  rectangle: 125,-400 500,-275
  lines w7: 0,-275 1000,-275 ; 125,-400 125,-150 ; 250,-400 250,-150 ; 500,-400 500,-150 ; 750,-400 750,-150 ; 0,-400 1000,-400 1000,-150 0,-150 0,-400
  text ".Layer_Name" at 577,-858.49 h60
M3 3D STEP Top:
  text ".Layer_Name" at 577,-858.49 h60
M4 3D STEP Bottom:
  text ".Layer_Name" at 577,-858.49 h60
M5 Assembly Top:
  lines w10: -292,-930.17 6308,-930.17 ; -292,-726.83 6310,-726.83 ; -292,-523.5 -292,-1133.5 3713,-1133.5 6310,-1133.5 6310,-523.5 -291.5,-523.5 -291.5,-1133.5 1284,-1133.5 ; 2173,-1133.5 2173,-523.5 ; 3440,-726.83 3440,-523.5 ; 4280,-726.83 4280,-523.5 ; 4902,-1140 4902,-937.17
  text "COMPONENTS MARKED 'DNP' SHOULD NOT BE POPULATED." at 1153.5,-318.5 h60
  text "ASSEMBLY VARIANT:" at 1153,-434 h60
  text ".VariantName" at 2189,-434 h60
  text "PCB VIEWED FROM TOP SIDE" at -228.5,-655.67 h60
  text "BOARD #:" at 2248,-655.67 h60
  text ".PRJ_Number" at 2793.5,-655.67 h60
  text "REV:" at 3638,-655.67 h60
  text ".PCB_Rev" at 3929.5,-655.67 h60
  text "SVN REV:" at 4476,-655.67 h60
  text ".VersionControl_RevNumber" at 4982,-655.67 h60
  text "TID #:" at 2248,-859 h60
  text ".TID" at 2793.5,-859 h60
  text "PLOT NAME =" at -228.5,-1064.34 h60
  text ".plot_File_Name" at 577,-1064.34 h60
  text "GENERATED    :" at 2250,-1064.34 h60
  text ".Print_Date" at 3119.5,-1064.34 h60
  text ".Print_Time" at 3848.5,-1064.34 h60
  text "TEXAS INSTRUMENTS" at 5113,-1064.34 h60
M6 Assembly Bottom:
  lines w10: -292.5,-727.33 6309.5,-727.33 ; -290.5,-930.67 6309.5,-930.67 ; 1115.5,-1140.5 1115.5,-937.67 ; 1737.5,-727.33 1737.5,-524 ; 2577.5,-727.33 2577.5,-524 ; 3844.5,-1134 3844.5,-524 ; 4733.5,-1134 6309,-1134 6309,-524 -292.5,-524 -292.5,-1134 2304.5,-1134 6309.5,-1134 6309.5,-524
  text "COMPONENTS MARKED 'DNP' SHOULD NOT BE POPULATED." at 6102,-318 h60
  text ".VariantName" at 5058,-434 h60
  text "ASSEMBLY VARIANT:" at 6097,-434 h60
  text ".VersionControl_RevNumber" at 1035.5,-656.17 h60
  text "SVN REV:" at 1541.5,-656.17 h60
  text ".PCB_Rev" at 2088,-656.17 h60
  text "REV:" at 2379.5,-656.17 h60
  text ".PRJ_Number" at 3224,-656.17 h60
  text "BOARD #:" at 3769.5,-656.17 h60
  text "PCB VIEWED FROM BOTTOM SIDE" at 6246,-656.17 h60
  text ".TID" at 3224,-859.5 h60
  text "TID #:" at 3769.5,-859.5 h60
  text "TEXAS INSTRUMENTS" at 904.5,-1064.84 h60
  text ".Print_Time" at 2169,-1064.84 h60
  text ".Print_Date" at 2898,-1064.84 h60
  text "GENERATED    :" at 3767.5,-1064.84 h60
  text ".plot_File_Name" at 5440.5,-1064.84 h60
  text "PLOT NAME =" at 6246,-1064.84 h60
M9 Title Sheet:
  drawing of 57 lines, arcs and shapes, not listed
  text "1" at 739.84,8036.5 h70
  text "2" at 3235.5,8036.5 h70
  text "3" at 5724.84,8036.5 h70
  text "4" at 8231.51,8036.5 h70
  text "5" at 10730.5,8036.5 h70
  text "6" at 13235.5,8036.5 h70
  text "A" at -416.5,6893.5 h70
  text "A" at 14383.5,6893.5 h70
  text "B" at -416.5,4513.5 h70
  text "B" at 14383.5,4513.5 h70
  text "C" at -416.5,2138.5 h70
  text "C" at 14383.5,2138.5 h70
  text "PROJECT TITLE:" at 11343.5,277.5 h45
  text ".PRJ_Title" at 11393.5,144.17 h70
  text "DESIGNED FOR:" at 11343.5,-23.5 h45
  text ".PRJ_Customer" at 11393.5,-163.5 h70
  text "D" at -416.5,-231.5 h70
  text "D" at 14383.5,-231.5 h70
  text "FILE NAME:" at 11343.5,-323.5 h45
  text ".PCB_File_Name_No_Path" at 11393.5,-443.5 h70
  text "Texas Instruments (TI) and/or its licensors do not warrant the accuracy or completeness of this specification" at 6374,-605.34 h45
  text "ENGINEER:" at 11343.5,-613.5 h45
  text "LAYOUT BY:" at 12848.5,-613.5 h45
  text "or any information contained therein. TI and/or its licensors do not warrant that this design will meet" at 6329.01,-718 h45
  text ".PRJ_Engineer" at 11393.5,-768.49 h70
  text ".PCB_Layout" at 12899,-768.49 h70
  text "the specifications, will be suitable for your application or fit for any particular purpose, or will operate in" at 6329.01,-830.67 h45
  text ".Layer_Name" at 577,-858.49 h60
  text "ALTIUM DESIGNER VERSION:" at 12848.5,-923.5 h45
  text "an implementation. TI and/or its licensors do not warrant that the design is production worthy. You should" at 6329.01,-943.33 h45
  text "completely validate and test your design implementation to confirm the system functionality for your application." at 6374,-1056 h45
  text ".print_Scale" at 11393.5,-1056.83 h70
  text ".Application_BuildNumber" at 12899,-1056.83 h70
  text "1" at 739.84,-1263.5 h70
  text "2" at 3235.5,-1263.5 h70
  text "3" at 5724.84,-1263.5 h70
  text "4" at 8231.51,-1263.5 h70
  text "5" at 10730.5,-1263.5 h70
  text "6" at 13235.5,-1263.5 h70
M10 Fab Notes:
  drawing of 189 lines, arcs and shapes, not listed
  text "DESIGN INFORMATION" at 12382.02,6356.17 h60
  text "MIN. TRACK WIDTH:" at 11737.46,6224.05 h60
  text "8" at 12833.7,6224.05 h60
  text "MIL" at 12988.46,6224.05 h60
  text "7.874" at 12667.32,6102.36 h60
  text "MIN. CLEARANCE:" at 11737.46,6099.92 h60
  text "MIL" at 12988.46,6099.92 h60
  text "MIN. VIA PAD SIZE:" at 11737.46,5975.8 h60
  text "24" at 12803.71,5975.8 h60
  text "MIL" at 12988.46,5975.8 h60
  text "0.05mm (2MIL)" at 12432.46,5845.9 h60
  text "MINIMUM ANNULAR RING" at 11408.23,5837.67 h60
  text "EXTERNAL" at 13140.46,5837.67 h60
  text "PER" at 11608.23,5727.55 h60
  text "IPC-D-275 CLASS 2 LEVEL C" at 11828.23,5727.54 h60
  text "MIL, HOLES" at 13316.46,5627.07 h60
  text "+/-" at 12924,5618.48 h60
  text "+/-" at 13778,5618.48 h60
  text "REGISTRATION TOLERANCES:" at 11408.23,5617.42 h60
  text "METAL" at 12608,5617.42 h60
  text "5" at 13184.2,5617.42 h60
  text "3" at 14017.2,5617.42 h60
  text "MIL" at 14133.46,5617.42 h60
  text "HOLE SIZE TOLERANCE (UNLESS OTHERWISE SPECIFIED):" at 11408.23,5519.1 h60
  text "+/-" at 13778,5516.23 h60
  text "3" at 14017.2,5515.17 h60
  text "MIL" at 14133.46,5515.17 h60
  text "MATERIAL:" at 11333.46,5377.52 h60
  text "FR-4 High Tg" at 12319.9,5249 h60
  text "X" at 12175.46,5241.01 h60
  text "FR-408" at 11754.46,5236.49 h60
  text "OTHER" at 13242.46,5236.49 h60
  text "62 MIL (1.6mm) +/-10%" at 12074.56,5093.46 h60
  text "X" at 11954.46,5091.01 h60
  text "THICKNESS:" at 11408.23,5085.24 h60
  text "OTHER" at 13359.46,5085.24 h60
  text "TOLERANCE:" at 11408.23,4946.92 h60
  text "X" at 12256.46,4946.92 h60
  text "ANSI IPC-6012 TYPE 3 CLASS 2" at 12434.48,4946.92 h60
  text "OTHER +/-" at 12434.46,4802.73 h60
  text "BOW & TWIST:" at 11408.23,4657.54 h60
  text "X" at 12256.46,4657.54 h60
  text "ANSI IPC-6012 TYPE 3 CLASS 2" at 12434.48,4657.54 h60
  text "OTHER +/-" at 12434.46,4510.85 h60
  text "DRILLING:" at 11333.46,4380.23 h60
  text "NC_DRILL FILES" at 13094.46,4275.04 h60
  text "REFERENCE:" at 11408.23,4271.1 h60
  text "X" at 12065.46,4271.01 h60
  text "AS SHOWN" at 12243.46,4271.1 h60
  text "X" at 12966.46,4271.1 h60
  text "X" at 13297.24,4128.85 h60
  text "OTHER" at 13392.46,4128.85 h60
  text "2 oz" at 13780.98,4127.79 h60
  text "PTH COPPER THICKNESS:" at 11407.91,4125.32 h60
  text "20-30 um" at 12675.14,4125.32 h60
  text "BOARD FINISH:" at 11333.46,3977.73 h60
  text "SILKSCREEN:" at 11488.68,3867.6 h60
  text "X" at 12446.46,3867.6 h60
  text "TOP" at 12563.46,3867.6 h60
  text "X" at 12956.46,3867.6 h60
  text "BOTTOM" at 13074.46,3867.6 h60
  text "SILKSCREEN COLOR:" at 11488.68,3712.41 h60
  text "X" at 12445.46,3712.41 h60
  text "WHITE" at 12563.46,3712.41 h60
  text "OTHER" at 13074.46,3712.41 h60
  text "X" at 12576.46,3568.96 h60
  text "GREEN" at 12694.46,3568.96 h60
  text "OTHER" at 13312.46,3568.96 h60
  text "SOLDER RESIST COLOR:" at 11488.68,3562.1 h60
  text "X" at 12576.46,3414.71 h60
  text "MATTE" at 12694.46,3414.71 h60
  text "SEMI-GLOSS" at 13312,3414.07 h60
  text "IMMERSION GOLD (ENIG)" at 12394.46,3241.94 h60
  text "ENEPIG" at 13732,3234.72 h60
  text "SURFACE FINISH:" at 11333.46,3233.72 h60
  text "IMM. TIN/SILVER OR EQUIV" at 11663,3096.4 h60
  text "OTHER" at 13094.46,3092.47 h60
  text "ARRAY/PANEL:" at 11333.46,2937.09 h60
  text "CUT AND TRIM PER M1 BOARD OUTLINE" at 12394.46,2928.87 h60
  text "N.C. ROUTE" at 12394.46,2792.9 h60
  text "V. SCORE" at 13260.46,2792.9 h60
  text "CERTIFICATION:" at 11333.46,2663.77 h60
  text "MATERIALS AND WORKMANSHIP FOR ALL PCBS" at 12058.46,2663.77 h60
  text "TO MEET OR EXCEED THE REQUIREMENTS OF:" at 12058.46,2569.71 h60
  text "ANSI IPC-A-600F CLASS ->" at 11823.96,2441.08 h60
  text "2" at 13581.96,2441.08 h60
  text "1" at 13266.96,2439.58 h60
  text "3" at 13935.96,2439.58 h60
  text "RoHS" at 12635.96,2293.39 h60
  text "OTHER" at 13280.36,2293.39 h60
  text "PER ORDER" at 13677.42,2293.39 h60
  text "ALL BOARDS MUST MEET OR EXCEED UL94-V0 REQUIREMENTS." at 11361,2139.57 h60
  text "PCB MUST BEAR THE UL94V-0 UL REGISTERED MATERIAL ID NUMBER" at 11361,2023.5 h60
  text "ADDITIONAL REQUIREMENTS:" at 11333.46,1854.08 h60
  text "MICROSECTION:" at 11408.23,1746.95 h60
  text "YES" at 12313.96,1746.95 h60
  text "REQUIRED" at 13175.46,1602.62 h60
  text "BARE BOARD ELEC. TEST:" at 11408.23,1599.76 h60
  text "NONE" at 12713.96,1599.76 h60
  text "PER ORDER" at 13767.46,1599.76 h60
  text "XX MIL VIAS REQUIRE NON-CONDUCTIVE FILL AND PLANARIZE" at 11576.38,1394.82 h59
  text "XX MIL VIAS REQUIRE CONDUCTIVE FILL AND PLANARIZE" at 11584.38,1290.84 h60
  text "OUTER XX MIL TRACES REQUIRE 50 OHM SINGLE-ENDED IMPEDANCE" at 11583.39,1127.46 h58
  text "LAYER 2 & 3 (INNER LAYERS) XX MIL WIDE, XX MIL SPACE / TRACES REQUIRE 100 OHM DIFFERENTIAL IMPEDANCE" at 11575.39,891.74 h60
  text ".Layer_Name" at 577,-858.49 h60
M11 Gerber Information:
  lines w10: -292,-930.17 6308,-930.17 ; -292,-726.83 6310,-726.83 ; -292,-523.5 -292,-1133.5 3713,-1133.5 6310,-1133.5 6310,-523.5 -291.5,-523.5 -291.5,-1133.5 1284,-1133.5 ; 2173,-1133.5 2173,-523.5 ; 3440,-726.83 3440,-523.5 ; 4280,-726.83 4280,-523.5 ; 4902,-1140 4902,-937.17
  text "ALL ARTWORK VIEWED FROM TOP SIDE" at -228.5,-655.67 h60
  text "BOARD #:" at 2248,-655.67 h60
  text ".PRJ_Number" at 2793.5,-655.67 h60
  text "REV:" at 3638,-655.67 h60
  text ".PCB_Rev" at 3929.5,-655.67 h60
  text "SVN REV:" at 4476,-655.67 h60
  text ".VersionControl_RevNumber" at 4982,-655.67 h60
  text "LAYER NAME =" at -228.5,-858.49 h60
  text "TID #:" at 2248,-859 h60
  text ".TID" at 2793.5,-859 h60
  text "PLOT NAME =" at -228.5,-1064.34 h60
  text ".plot_File_Name" at 577,-1064.34 h60
  text "GENERATED    :" at 2250,-1064.34 h60
  text ".Print_Date" at 3119.5,-1064.34 h60
  text ".Print_Time" at 3848.5,-1064.34 h60
  text "TEXAS INSTRUMENTS" at 5113,-1064.34 h60
M12 Stackup:
  drawing of 295 lines, arcs and shapes, not listed
  text "Layer" at 6197.12,4421.26 h60
  text "Name" at 6607.03,4421.26 h60
  text "Material" at 7536.78,4421.26 h60
  text "Thickness" at 8396.54,4421.26 h60
  text "Constant" at 9046.38,4421.26 h60
  text "Board Layer Stack" at 9616.24,4421.26 h60
  text "Top Overlay" at 6607.03,4301.26 h60
  text "Top Solder" at 6607.03,4181.26 h60
  text "Solder Resist" at 7536.78,4181.26 h60
  text "0.40mil" at 8396.54,4181.26 h60
  text "3.5" at 9046.38,4181.26 h60
  text "1" at 6197.12,4061.26 h60
  text "Top Layer" at 6607.03,4061.26 h60
  text "CF-005" at 7536.78,4061.26 h60
  text "2.76mil" at 8396.54,4061.26 h60
  text "Dielectric 1" at 6607.03,3941.26 h60
  text "PP-006" at 7536.78,3941.26 h60
  text "2.80mil" at 8396.54,3941.26 h60
  text "4.1" at 9046.38,3941.26 h60
  text "2" at 6197.12,3821.26 h60
  text "GND" at 6607.03,3821.26 h60
  text "CF-004" at 7536.78,3821.26 h60
  text "1.38mil" at 8396.54,3821.26 h60
  text "Dielectric1" at 6607.03,3701.26 h60
  text "FR-4 High Tg" at 7536.78,3701.26 h60
  text "59.20mil" at 8396.54,3701.26 h60
  text "4.8" at 9046.38,3701.26 h60
  text "3" at 6197.12,3581.26 h60
  text "PWR" at 6607.03,3581.26 h60
  text "CF-004" at 7536.78,3581.26 h60
  text "1.38mil" at 8396.54,3581.26 h60
  text "Dielectric 2" at 6607.03,3461.26 h60
  text "PP-006" at 7536.78,3461.26 h60
  text "2.80mil" at 8396.54,3461.26 h60
  text "4.1" at 9046.38,3461.26 h60
  text "4" at 6197.12,3341.26 h60
  text "Bottom Layer" at 6607.03,3341.26 h60
  text "CF-005" at 7536.78,3341.26 h60
  text "2.76mil" at 8396.54,3341.26 h60
  text "Bottom Solder" at 6607.03,3221.26 h60
  text "Solder Resist" at 7536.78,3221.26 h60
  text "0.40mil" at 8396.54,3221.26 h60
  text "3.5" at 9046.38,3221.26 h60
  text "Bottom Overlay" at 6607.03,3101.26 h60
  text ".Layer_Name" at 577,-858.49 h60
M13 Component Bodies Top:
  text ".Layer_Name" at 577,-858.49 h60
M14 Component Bodies Bottom:
  text ".Layer_Name" at 577,-858.49 h60
M15 Courtyards Top:
  text ".Layer_Name" at 577,-858.49 h60
M16 Courtyards Bottom:
  text ".Layer_Name" at 577,-858.49 h60
Drill Drawing:
  circle w10: c4768.17,10471.41 r17.23
  circle w10: c4768.17,10471.41 r28.72
  circle w10: c4768.17,9825.17 r28.72
  lines w10: 4739.45,9537.95 4768.17,9552.31 4796.89,9537.95 4782.53,9566.67 4796.89,9595.39 4768.17,9581.03 4739.45,9595.39 4753.81,9566.67 4739.45,9537.95 ; 4739.45,9681.56 4753.81,9681.56 4753.81,9667.2 4782.53,9667.2 4782.53,9681.56 4796.89,9681.56 4796.89,9710.28 4782.53,9710.28 4782.53,9724.64 4753.81,9724.64 4753.81,9710.28 4739.45,9710.28 4739.45,9681.56 ; 4739.45,9983.14 4796.89,9983.14 4768.17,9925.69 4739.45,9983.14 ; 4739.45,10069.3 4753.81,10069.3 4753.81,10054.94 4782.53,10054.94 4782.53,10069.3 4796.89,10069.3 4796.89,10098.02 4782.53,10098.02 4782.53,10112.38 4753.81,10112.38 4753.81,10098.02 4739.45,10098.02 4739.45,10069.3 ; 4739.45,10184.19 4796.89,10184.19 4796.89,10241.63 4739.45,10241.63 4739.45,10184.19 ; 4739.45,10342.16 4768.17,10313.44 4796.89,10342.16 4768.17,10370.88 4739.45,10342.16 ; 4739.45,10629.38 4796.89,10629.38 4768.17,10571.93 4739.45,10629.38 ; 4739.45,10701.18 4768.17,10715.54 4796.89,10701.18 4782.53,10729.9 4796.89,10758.62 4768.17,10744.26 4739.45,10758.62 4753.81,10729.9 4739.45,10701.18 ; 4739.45,10830.43 4796.89,10830.43 4796.89,10887.87 4739.45,10887.87 4739.45,10830.43 ; 4739.45,10959.68 4739.45,10974.04 4753.81,10988.4 4739.45,11002.76 4739.45,11017.12 4753.81,11017.12 4768.17,11002.76 4782.53,11017.12 4796.89,11017.12 4796.89,11002.76 4782.53,10988.4 4796.89,10974.04 4796.89,10959.68 4782.53,10959.68 4768.17,10974.04 4753.81,10959.68 4739.45,10959.68 ; 4739.45,11103.28 4753.81,11103.28 4768.17,11088.92 4782.53,11103.28 4796.89,11103.28 4782.53,11117.65 4796.89,11132.01 4782.53,11132.01 4768.17,11146.37 4753.81,11132.01 4739.45,11132.01 4753.81,11117.65 4739.45,11103.28 ; 4750.94,9549.44 4768.17,9558.05 4785.4,9549.44 4776.78,9566.67 4785.4,9583.9 4768.17,9575.29 4750.94,9583.9 4759.55,9566.67 4750.94,9549.44 ; 4750.94,9687.3 4759.55,9687.3 4759.55,9678.68 4776.78,9678.68 4776.78,9687.3 4785.4,9687.3 4785.4,9704.53 4776.78,9704.53 4776.78,9713.15 4759.55,9713.15 4759.55,9704.53 4750.94,9704.53 4750.94,9687.3 ; 4750.94,10617.89 4785.4,10617.89 4768.17,10583.42 4750.94,10617.89 ; 4750.94,10841.92 4785.4,10841.92 4785.4,10876.38 4750.94,10876.38 4750.94,10841.92
  lines w12: 4687.49,9499.17 8045.88,9499.17 ; 4687.49,11179.4 8045.88,11179.4 ; 5038.61,9369.93 5038.61,11308.65 ; 5383.62,9369.93 5383.62,11308.65 ; 6045.08,9369.93 6045.08,11308.65 ; 6314.38,9369.93 6314.38,11308.65 ; 6704.23,9369.93 6704.23,11308.65 ; 7457.27,9369.93 7457.27,11308.65 ; 4687.49,9369.93 8045.88,9369.93 8045.88,11308.65 4687.49,11308.65 4687.49,9369.93
  text "Symbol" at 4765.04,11218.17 h74.8
  text "Quantity" at 5077.39,11218.17 h74.8
  text "Finished Hole Size" at 5422.39,11218.17 h74.8
  text "Plated" at 6083.85,11218.17 h74.8
  text "Hole Type" at 6353.15,11218.17 h74.8
  text "Drill Layer Pair" at 6743,11218.17 h74.8
  text "Hole Tolerance" at 7496.05,11218.17 h74.8
  text "116" at 5077.39,11088.92 h62.33
  text "7.87mil (0.200mm)" at 5422.39,11088.92 h62.33
  text "PTH" at 6083.85,11088.92 h62.33
  text "Round" at 6353.15,11088.92 h62.33
  text "Top Layer - Bottom Layer" at 6743,11088.92 h62.33
  text "2" at 5077.39,10959.68 h62.33
  text "8.00mil (0.203mm)" at 5422.39,10959.68 h62.33
  text "PTH" at 6083.85,10959.68 h62.33
  text "Round" at 6353.15,10959.68 h62.33
  text "Top Layer - Bottom Layer" at 6743,10959.68 h62.33
  text "107" at 5077.39,10830.43 h62.33
  text "10.00mil (0.254mm)" at 5422.39,10830.43 h62.33
  text "PTH" at 6083.85,10830.43 h62.33
  text "Round" at 6353.15,10830.43 h62.33
  text "Top Layer - Bottom Layer" at 6743,10830.43 h62.33
  text "18" at 5077.39,10701.18 h62.33
  text "11.81mil (0.300mm)" at 5422.39,10701.18 h62.33
  text "PTH" at 6083.85,10701.18 h62.33
  text "Round" at 6353.15,10701.18 h62.33
  text "Top Layer - Bottom Layer" at 6743,10701.18 h62.33
  text "19" at 5077.39,10571.93 h62.33
  text "12.00mil (0.305mm)" at 5422.39,10571.93 h62.33
  text "PTH" at 6083.85,10571.93 h62.33
  text "Round" at 6353.15,10571.93 h62.33
  text "Top Layer - Bottom Layer" at 6743,10571.93 h62.33
  text "13" at 5077.39,10442.68 h62.33
  text "14.00mil (0.356mm)" at 5422.39,10442.68 h62.33
  text "PTH" at 6083.85,10442.68 h62.33
  text "Round" at 6353.15,10442.68 h62.33
  text "Top Layer - Bottom Layer" at 6743,10442.68 h62.33
  text "281" at 5077.39,10313.44 h62.33
  text "15.00mil (0.381mm)" at 5422.39,10313.44 h62.33
  text "PTH" at 6083.85,10313.44 h62.33
  text "Round" at 6353.15,10313.44 h62.33
  text "Top Layer - Bottom Layer" at 6743,10313.44 h62.33
  text "37" at 5077.39,10184.19 h62.33
  text "40.00mil (1.016mm)" at 5422.39,10184.19 h62.33
  text "PTH" at 6083.85,10184.19 h62.33
  text "Round" at 6353.15,10184.19 h62.33
  text "Top Layer - Bottom Layer" at 6743,10184.19 h62.33
  text "4" at 5077.39,10054.94 h62.33
  text "40.16mil (1.020mm)" at 5422.39,10054.94 h62.33
  text "PTH" at 6083.85,10054.94 h62.33
  text "Round" at 6353.15,10054.94 h62.33
  text "Top Layer - Bottom Layer" at 6743,10054.94 h62.33
  text "8" at 5077.39,9925.69 h62.33
  text "49.21mil (1.250mm)" at 5422.39,9925.69 h62.33
  text "PTH" at 6083.85,9925.69 h62.33
  text "Round" at 6353.15,9925.69 h62.33
  text "Top Layer - Bottom Layer" at 6743,9925.69 h62.33
  text "28" at 5077.39,9796.44 h62.33
  text "63.00mil (1.600mm)" at 5422.39,9796.44 h62.33
  text "PTH" at 6083.85,9796.44 h62.33
  text "Round" at 6353.15,9796.44 h62.33
  text "Top Layer - Bottom Layer" at 6743,9796.44 h62.33
  text "1" at 5077.39,9667.2 h62.33
  text "31.50mil (0.800mm)" at 5422.39,9667.2 h62.33
  text "PTH" at 6083.85,9667.2 h62.33
  text "Slot" at 6353.15,9667.2 h62.33
  text "Top Layer - Bottom Layer" at 6743,9667.2 h62.33
  text "5" at 5077.39,9537.95 h62.33
  text "31.50mil (0.800mm)" at 5422.39,9537.95 h62.33
  text "PTH" at 6083.85,9537.95 h62.33
  text "Slot" at 6353.15,9537.95 h62.33
  text "Top Layer - Bottom Layer" at 6743,9537.95 h62.33
  text "639 Total" at 5077.39,9408.7 h62.33
  text "Slot definitions :" at 4765.04,9318.23 h62.33
  text "Routed Path Length" at 5233.62,9318.23 h62.33
  text "= Calculated from tool start centre position to tool end centre position." at 5794.76,9318.23 h62.33
  text "Hole Length" at 5233.62,9266.53 h62.33
  text "= Routed Path Length + Tool Size = Slot length as defined in the PCB layout" at 5587.04,9266.53 h62.33
  text ".Layer_Name" at 577,-858.49 h60
M17 Embedded Cavity:
  text ".Layer_Name" at 577,-858.49 h60
M18 Embedded Assembly:
  text ".Layer_Name" at 577,-858.49 h60
M19 Embedded Keepout:
  text ".Layer_Name" at 577,-858.49 h60

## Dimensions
0,-400 to 1000,-400 on M2 Board Dimensions
-9.84,78.74 to -9.84,5452.76 on M2 Board Dimensions
-9.84,78.74 to 5118.11,78.74 on M2 Board Dimensions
